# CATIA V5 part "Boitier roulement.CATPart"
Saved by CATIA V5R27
Part number: Boitier roulement
Material "Acier": density 7860 kg/m3, Young's modulus 2e+11 Pa, Poisson ratio 0.266, thermal expansion 1.17e-05 1/K
Bounding box of the stored display mesh (mm): x -19.05 to 19.05, y -85 to 85, z 0 to 70.4
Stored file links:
  \\triton.meca.polymtl.ca\usagers\zaoue\profiles\Desktop\varm_ass\bearing assy\Boitier roulement.CATPart
  C:\Program Files\Dassault Systemes\B27\win_b64\startup\materials\brushed_metal1.jpg
  C:\Program Files\Dassault Systemes\B27\win_b64\startup\materials\brushed_metal2.jpg
  C:\Program Files\Dassault Systemes\B27\win_b64\startup\materials\eroded_metal_1.jpg
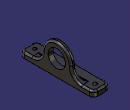
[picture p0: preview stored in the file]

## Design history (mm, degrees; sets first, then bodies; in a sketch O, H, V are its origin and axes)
Parameters
  `epaisseur du mur` = 12.7 mm
  `diametre roulement` = 40 mm
  `Distance entre trous de vis` = 140 mm
  `pince de la vis` = 15 mm
  `epaisseur flange` = 38.1 mm
  `epaisseur roulement` = 12 mm
Body1 (main body), material "Acier"
  Sketch1 on yz-plane, origin (0, 0, 0), H (0, 1, 0), V (0, 0, 1)
    point P1 (85, 0)
    line L1 (85, 0) -> (-85, 0)
    line L2 (-85, 0) -> (-85, 12.7)
    line L3 (-85, 12.7) -> (-57.7, 12.7)
    arc A1 centre (-57.7, 37.7) radius 25 from (-57.7, 12.7) to (-32.7, 37.7) ccw
    arc A2 centre (0, 37.7) radius 32.7 from (-32.7, 37.7) to (32.7, 37.7) cw
    point P7 (0, 37.7)
    arc A3 centre (57.7, 37.7) radius 25 from (32.7, 37.7) to (57.7, 12.7) ccw
    point P10 (57.7, 12.7)
    line L4 (57.7, 12.7) -> (85, 12.7)
    line L5 (85, 12.7) -> (85, 0)
    construction circle A4 centre (0, 37.7) radius 20
    reference intersected line E1 through (0, 0) direction (0, 1) from zx-plane
    construction line L6 (-57.7, 37.7) -> (57.7, 37.7)
    point P12 (70, 12.7)
    point P13 (-70, 12.7)
    radius A2 = 32.7 {= Sketch1.radius(A4)+`epaisseur du mur`}
    radius A4 = 20 {= `diametre roulement` /2}
    distance L4 L1 = 12.7 {= `epaisseur du mur`}
    distance P12 P13 = 140 {= `Distance entre trous de vis`}
    distance L2 P13 = 15 {= `pince de la vis`}
    distance L5 P12 = 15 {= Sketch1.distance(L2 P13)}
    distance L2 P7 = 85 (reference)
    distance P7 L5 = 85 {= Sketch1.distance(L2 P7)}
    distance A4 L4 = 5
    coincidence: P1 H, P10 L3, P7 E1, P7 L6, P12 L4, P13 L3
    horizontal: L1 H, L3 H, L6 H
    vertical: L2 V, L5 V
    tangency: A1 L3, A2 A1, A3 L3, A3 A2, L4 A3
  Pad1: profile Sketch1, direction (1, 0, 0), length 19.05 {= `epaisseur flange`/2}, mirrored extent
  Sketch2 on zx-plane, origin (0, 0, 0), H (-1, 0, 0), V (0, 0, 1)
    intersected line E1 (-19.05, 70.4) -> (19.05, 70.4) from face of Pad1 from Sketch1.A2
    intersected line E2 (-19.05, 70.4) -> (-7.05, 70.4) from face of Pad1 from Sketch1.A2
    point P3 (-19.05, 70.4)
    line L1 (-19.05, 70.4) -> (-19.05, 0.5664)
    point P4 (-7.05, 70.4)
    line L2 (-7.05, 70.4) -> (-7.05, 12.7)
    reference projected curve E3 from face of Pad1 from Sketch1.L5
    point P5 (19.05, 0)
    point P6 (19.05, 0)
    distance L1 L2 = 12 {= `epaisseur roulement`}
    distance L1 E3 = 0
    coincidence: P3 E1, P4 E1, P5 P6
  Pocket1: profile Sketch2, direction (0, 1, 0), through (limit type 3), opposite side through (limit type 3), outer side
  Sketch3 on face of Pocket1, origin (0.6062, 77.3651, 12.7), H (1, 0, 0), V (0, 1, 0)
    point P1 (-0.6062, -7.3651)
    construction line L1 (-0.6062, -7.3651) -> (-0.6062, -183.9494)
    point P2 (-0.6062, -7.3651)
    point P3 (-0.6062, -183.9494)
    reference intersected line E1 through (-0.6062, 0) direction (0, 1) from yz-plane
    point P4 (-0.6062, -183.9494)
    reference intersected line E2 through (0, -77.3651) direction (-1, 0) from zx-plane
    distance P1 E2 = 70 {= `Distance entre trous de vis`/2}
    vertical: L1 V
    coincidence: L1 E1, P2 P1, P4 P3
  Hole1: placed by Sketch3, at (0, 70, 12.7) direction (0, 0, -1), diameter 8.332, through (limit type 6)
  RectPattern1: of Hole1, direction 1 instances 2, spacing 140 {= `Distance entre trous de vis`}, along edge [start face of Pad1 | face of Pocket1]
  Fillet1: radius 10, on edge [face of Pad1 from Sketch1.L2 | end face of Pad1]; edge [start face of Pad1 | face of Pad1 from Sketch1.L2]; edge [face of Pad1 from Sketch1.L5 | end face of Pad1]; edge [start face of Pad1 | face of Pad1 from Sketch1.L5]
  Fillet2: radius 4, on edge [face of Pad1 from Sketch1.A3 | face of Pocket1 from Sketch2.L2]; edge [face of Pocket1 from Sketch2.L2 | face of Pad1]; edge [face of Pad1 | end face of Pad1]
  Sketch4 on face of Pocket1 from Sketch2.L2, origin (7.05, -4.379, 62.2373), H (0, 1, 0), V (0, 0, -1)
    point P1 (4.379, 24.5373)
    reference projected point E1 (4.379, 24.5373) from axis of face of Pad1 from Sketch1.A2
    coincidence: P1 E1
  Hole2: placed by Sketch4, at (7.05, 0, 37.7) direction (1, 0, 0), diameter 40 {= `diametre roulement`}, depth 12 {= `epaisseur roulement`}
